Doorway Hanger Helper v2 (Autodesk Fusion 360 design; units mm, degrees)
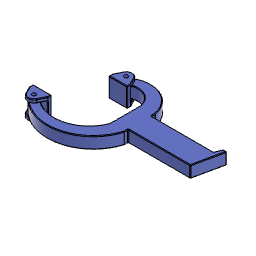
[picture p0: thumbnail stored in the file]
parameter "SwivelClearance" = 0.175
parameter "JointDiameter" = 7
sketch "Sketch1" plane through (0, 0, 0) normal (0, 0, 1) x axis (1, 0, 0)
  line L1 (-1.5943, 0) -> (0, 0)
  line L2 (-46.5943, 0) -> (-1.5943, 0)
  line L3 (0, -2.5) -> (0, 0)
  line L4 (8, -2.5) -> (0, -2.5)
  line L5 (8, -34.5) -> (8, -2.5)
  line L6 (6.259, -34.5) -> (8, -34.5)
  line L7 (0, -34.5) -> (6.259, -34.5)
  line L8 (0, -37) -> (0, -34.5)
  line L9 (-46.3163, -37) -> (0, -37)
  line L10 (-16.5943, 0) -> (-1.5943, 0)
  line L11 (-16.5943, 3) -> (-16.5943, 0)
  line L12 (-1.5943, 3) -> (-1.5943, 0)
  line L13 (-4.625, 9.0419) -> (-1.5943, 3)
  line L14 (-13.5635, 9.0419) -> (-16.5943, 3)
  line L15 (-1.5943, 3) -> (-16.5943, 3)
  arc A1 centre (-9.0943, 6.8) radius 5 clockwise from (-13.5635, 9.0419) to (-4.625, 9.0419)
  circle C1 centre (-9.0943, 6.8) radius 3.5
  point P1 (0, 0)
  point P2 (0, 0)
  point P5 (0, 0)
  point P6 (0, -2.5)
  point P10 (0, -34.5)
  point P13 (-16.5943, 0)
  point P14 (-16.5943, 3)
  point P16 (-1.5943, 3)
  point P19 (-9.0943, 0)
  point P18 (-9.0943, 6.8)
  point P3 (-1.5943, 0)
  point P4 (-46.5943, 0)
  point P7 (8, -2.5)
  point P11 (0, -37)
  point P8 (8, -34.5)
  coincident P1 P2
  horizontal L1
  parallel L1 L2
  coincident P1 P5
  perpendicular L1 L3
  perpendicular L3 L4
  perpendicular L1 L5
  perpendicular L5 L6
  perpendicular L3 L7
  perpendicular L7 L8
  perpendicular L8 L9
  equal L3 L8
  vertical P6 P10
  coincident L2 P13
  perpendicular L10 L11
  perpendicular L10 L12
  horizontal P14 P16
  midpoint L10 P19
  vertical P18 P19
  concentric A1 C1
  tangent L13 A1
  tangent A1 L14
  dimension "d1" distance P3 P4 = 45
  dimension "d2" distance P6 P7 = 8
  dimension "d3" distance P1 P11 = 37
  dimension "d4" distance P7 P8 = 32
  dimension "d5" distance P3 P13 = 15
  dimension "d6" distance P13 P14 = 3
  dimension "d8" radius A1 = 5
  dimension "d9" diameter C1 = 7 (= "JointDiameter")
  dimension "d10" distance P19 C1 = 3.3
extrude "Extrude1" new body sketch "Sketch1" profile of L10 L11 L12 L15 along normal blind 16 bodies "Foot"
extrude "Extrude2" add sketch "Sketch1" profile of L13 A1 L14 L15 along normal blind 3
extrude "Extrude3" sketch "Sketch1" profile of L13 A1 L14 L15 blind -3
fillet "Fillet1" radius 0.5
hole "Hole1" HoleDepth 12 HoleDiameter 3.12
work_plane "WorkPlane1" AlongDistance 0.175 (= "SwivelClearance")
sketch "Sketch2" plane through (-9.0943, 7.4, 12.825) normal (0, 0, -1) x axis (1, 0, 0)
  line L1 (-37.222, 44.4) -> (9.0943, 44.4)
  line L2 (17.0943, 9.9) -> (9.0943, 9.9)
  line L3 (17.0943, 41.9) -> (17.0943, 9.9)
  line L4 (9.0943, 41.9) -> (15.3532, 41.9)
  line L5 (9.0943, 9.9) -> (9.0943, 7.4)
  line L6 (7.5, 7.4) -> (9.0943, 7.4)
  line L7 (15.3532, 41.9) -> (17.0943, 41.9)
  line L8 (9.0943, 44.4) -> (9.0943, 41.9)
  line L9 (23.0943, 11.9) -> (35.0943, 11.9)
  line L10 (23.0943, 37.3) -> (23.0943, 11.9)
  line L11 (35.0943, 37.3) -> (23.0943, 37.3)
  line L12 (35.0943, 11.9) -> (35.0943, 37.3)
  line L13 (85.8943, 15.075) -> (35.0943, 15.075)
  line L14 (85.8943, 34.125) -> (85.8943, 15.075)
  line L15 (35.0943, 34.125) -> (85.8943, 34.125)
  line L16 (35.0943, 15.075) -> (35.0943, 34.125)
  line L17 (88.1419, 9.5119) -> (85.8943, 15.075)
  line L18 (91.1419, 9.5119) -> (88.1419, 9.5119)
  line L19 (85.8943, 34.125) -> (91.1419, 9.5119)
  circle C1 centre (0, 0.6) radius 3.5
  circle C2 centre (0, 0.6) radius 3.5
  circle C3 centre (-24.722, 51.2) radius 3.5
  arc A1 centre (9.6591, 14.9154) radius 13.7694 clockwise from (23.0943, 11.9) to (1.9576, 3.5013)
  arc A2 centre (12.2417, 16.0738) radius 23.2306 clockwise from (35.0943, 11.9) to (-2.1715, -2.1449)
  arc A3 centre (-3.5412, 27.26) radius 28.4648 clockwise from (-22.4028, 48.5787) to (23.0943, 37.3)
  arc A4 centre (-1.0589, 26.4401) radius 37.749 clockwise from (-27.1402, 53.7303) to (35.0943, 37.3)
  point P8 (-24.722, 51.2)
  point P10 (-24.722, 51.2)
  point P29 (1.9576, 3.5013)
  point P31 (-2.1715, -2.1449)
  point P33 (-22.4028, 48.5787)
  point P35 (-27.1402, 53.7303)
  point P37 (35.0943, 15.075)
  point P41 (85.8943, 24.6)
  point P42 (23.0943, 24.6)
  point P2 (0, 0.6)
  point P6 (0, 7.4)
  point P7 (7.5, 7.4)
  point P4 (-37.222, 44.4)
  point P38 (85.8943, 15.075)
  point P40 (35.0943, 34.125)
  point P26 (23.0943, 11.9)
  point P27 (23.0943, 37.3)
  point P13 (17.0943, 9.9)
  point P25 (35.0943, 11.9)
  point P43 (88.1419, 9.5119)
  point P44 (91.1419, 9.5119)
  concentric C1 C2
  coincident P8 P10
  horizontal L9
  vertical L10
  horizontal L11
  vertical L12
  tangent C2 A1
  coincident C2 P29
  tangent C1 A2
  coincident C2 P31
  tangent C3 A3
  coincident C3 P33
  tangent C3 A4
  coincident C3 P35
  horizontal L13
  vertical L14
  horizontal L15
  vertical L16
  coincident L12 P37
  midpoint L14 P41
  midpoint L10 P42
  horizontal P41 P42
  perpendicular L14 L18
  dimension "d26" distance P2 P6 = 6.8
  dimension "d27" distance P6 P7 = 7.5
  dimension "d28" distance P4 P8 = 12.5 (= "d27 + 5 mm")
  dimension "d29" distance L1 P8 = 6.8 (= "d26")
  dimension "d30" diameter C2 = 7 (= "JointDiameter")
  dimension "d31" diameter C3 = 7 (= "JointDiameter")
  dimension "d32" distance P37 P38 = 50.8 (= "2")
  dimension "d33" distance P37 P40 = 19.05 (= "3  / 4")
  dimension "d34" distance P26 P27 = 25.4 (= "1")
  dimension "d35" distance P13 P26 = 2
  dimension "d36" distance P13 P26 = 6
  dimension "d37" distance P25 P26 = 12
  dimension "d38" distance P38 P43 = 6
  dimension "d39" distance P43 P44 = 3
  dimension "d40" angle L13 L17 = 112 (= "Angular Dimension-2")
extrude "Extrude4" new body sketch "Sketch2" profile of C1 C2 C3 L9 L10 L11 L12 A1 A2 A3 A4 L13 L14 L15 L16 L17 L18 L19 to an object offset 0.175 (= "SwivelClearance") bodies "Arm"
fillet "Fillet3" radius 0.5
hole "Hole2" HoleDepth 12 HoleDiameter 3.1
copy_paste_bodies "CopyPasteBodies1"
move "Move1" TranslateX 0 TranslateY 0 TranslateZ 0
align "Align1"
base_feature "Base Feature1"
align "Align1"
scale "Scale1" ScaleZ 1.2112
move "Move1" TranslateX 0 TranslateY 0 TranslateZ 0.25
copy_paste_bodies "CopyPasteBodies1"
move "Move2" TranslateX 0 TranslateY 0 TranslateZ 0
align "Align2"
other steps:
base_feature "Base Feature1" bodies "Foot", "Bottom Foot"
base_feature "Base Feature2"
create_component "CreateComponent1"
named bodies: "Foot", "Arm", "Bottom Foot"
